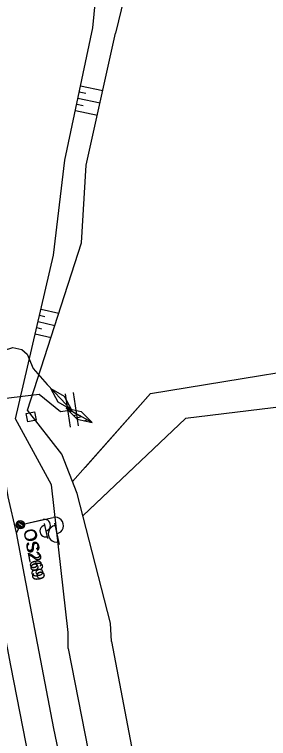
# Model space of a CAD drawing. Extents: x -545967 to -545044, y -1122650 to -1118491.
# Drawn here: x -545802.1 to -545771.9, y -1118710.2 to -1118624.1 of the extents above; entities that cross this region are included whole.
import ezdxf

# ---------------------------------------------------------------- set-up
doc = ezdxf.new("R2010")
doc.units = 0
for name, color, linetype in [('Vrstva 1', 7, 'Continuous'), ('Vrstva 25', 7, 'Continuous'), ('Vrstva 25 - silnoproud prvky', 7, 'Continuous'), ('Vrstva 26', 7, 'Continuous'), ('Vrstva 26 - silnoproud', 7, 'Continuous'), ('Vrstva 31', 7, 'Continuous'), ('Vrstva 41', 7, 'Continuous'), ('Vrstva 42', 7, 'Continuous'), ('Vrstva 48', 7, 'Continuous'), ('Vrstva 49', 7, 'Continuous'), ('Vrstva 62', 7, 'Continuous')]:
    doc.layers.add(name, color=color, linetype=linetype)

msp = doc.modelspace()

# ---------------------------------------------------------------- linework, layer by layer
at = {"layer": 'Vrstva 1'}
msp.add_lwpolyline([(-545803.343, -1118697.361), (-545802.529, -1118701.559), (-545796.372, -1118733.137), (-545788.892, -1118771.626), (-545784.123, -1118796.192), (-545777.723, -1118829.089), (-545771.163, -1118862.699), (-545764.792, -1118895.381), (-545757.603, -1118932.309), (-545753.441, -1118953.648), (-545749.904, -1118971.286), (-545746.403, -1118987.4), (-545742.64, -1119003.664), (-545739.307, -1119017.411), (-545735.997, -1119030.103), (-545730.526, -1119049.438)], dxfattribs=at)
at = {"layer": 'Vrstva 25'}
for p, q in [((-545800.899, -1118684.702), (-545797.485, -1118683.93)), ((-545801.866, -1118684.675), (-545801.056, -1118685.186)), ((-545801.635, -1118684.378), (-545800.891, -1118684.847)), ((-545797.331, -1118684.613), (-545796.758, -1118687.149))]:
    msp.add_line(p, q, dxfattribs=at)
msp.add_circle((-545801.387, -1118684.812), 0.5, dxfattribs=at)
msp.add_circle((-545801.387, -1118684.812), 0.5, dxfattribs=at)
for centre, start, end in [((-545797.265, -1118684.905), 282.73998, 102.73998), ((-545797.056, -1118685.883), 102.0374, 283.44255)]:
    msp.add_arc(centre, 1, start, end, dxfattribs=at)
at = {"layer": 'Vrstva 25 - silnoproud prvky'}
for p, q in [((-545801.722, -1118684.716), (-545801.156, -1118685.074)), ((-545801.56, -1118684.508), (-545801.04, -1118684.837)), ((-545801.046, -1118684.735), (-545798.656, -1118684.195)), ((-545798.548, -1118684.672), (-545798.147, -1118686.448))]:
    msp.add_line(p, q, dxfattribs=at)
msp.add_circle((-545801.387, -1118684.812), 0.35, dxfattribs=at)
for centre, start, end in [((-545798.356, -1118685.562), 102.0374, 283.44255), ((-545798.502, -1118684.877), 282.73998, 102.73998)]:
    msp.add_arc(centre, 0.7, start, end, dxfattribs=at)
at = {"layer": 'Vrstva 26'}
for points in [[(-545795.14, -1118719.856), (-545797.401, -1118709.038), (-545800.896, -1118690.8), (-545801.851, -1118685.761), (-545802.818, -1118681.484), (-545803.86, -1118675.25), (-545805.172, -1118668.631), (-545806.131, -1118665.54), (-545807.231, -1118660.35), (-545808.894, -1118651.177), (-545811.62, -1118637.176), (-545812.724, -1118631.013), (-545813.605, -1118626.947), (-545815.439, -1118615.53)], [(-545801.851, -1118685.761), (-545801.379, -1118684.924), (-545801.387, -1118684.812)]]:
    msp.add_lwpolyline(points, dxfattribs=at)
at = {"layer": 'Vrstva 26 - silnoproud'}
for points in [[(-545795.14, -1118719.856), (-545797.401, -1118709.038), (-545800.896, -1118690.8), (-545801.851, -1118685.761), (-545802.818, -1118681.484), (-545803.86, -1118675.25), (-545805.172, -1118668.631), (-545806.131, -1118665.54), (-545807.231, -1118660.35), (-545808.894, -1118651.177), (-545811.62, -1118637.176), (-545812.724, -1118631.013), (-545813.605, -1118626.947), (-545815.439, -1118615.53)], [(-545801.851, -1118685.761), (-545801.379, -1118684.924), (-545801.387, -1118684.812)]]:
    msp.add_lwpolyline(points, dxfattribs=at)
at = {"layer": 'Vrstva 31'}
for p, q in [((-545795.834, -1118671.051), (-545795.77, -1118671.046)), ((-545795.545, -1118671.356), (-545795.324, -1118671.291)), ((-545795.075, -1118671.822), (-545794.607, -1118671.686)), ((-545794.762, -1118672.119), (-545794.145, -1118671.941)), ((-545793.799, -1118672.443), (-545793.429, -1118672.335)), ((-545793.057, -1118672.602), (-545792.984, -1118672.58))]:
    msp.add_line(p, q, dxfattribs=at)
for points in [[(-545850.96, -1118681.13), (-545850.51, -1118680.46), (-545848.78, -1118676.81), (-545847.44, -1118674.83), (-545847.15, -1118673.7), (-545846.77, -1118673.1), (-545844.1, -1118672.89), (-545832.3, -1118671.48), (-545826.35, -1118670.63), (-545811.42, -1118666.68), (-545802.26, -1118663.75), (-545801.2, -1118663.96), (-545800.56, -1118664.54), (-545799.84, -1118666.21), (-545798.21, -1118668.15), (-545796.54, -1118669.87), (-545795.09, -1118671.42), (-545794.4, -1118671.8)], [(-545850.96, -1118681.13), (-545850.51, -1118680.46), (-545848.78, -1118676.81), (-545847.44, -1118674.83), (-545847.15, -1118673.7), (-545846.77, -1118673.1), (-545844.1, -1118672.89), (-545832.3, -1118671.48), (-545826.35, -1118670.63), (-545811.42, -1118666.68), (-545802.26, -1118663.75), (-545801.2, -1118663.96), (-545800.56, -1118664.54), (-545799.84, -1118666.21), (-545798.21, -1118668.15), (-545796.54, -1118669.87), (-545795.09, -1118671.42), (-545794.4, -1118671.8)], [(-545797.759, -1118668.614), (-545796.181, -1118669.522), (-545795.321, -1118671.126), (-545796.899, -1118670.218), (-545797.759, -1118668.614)], [(-545795.943, -1118670.95), (-545794.154, -1118671.354), (-545792.857, -1118672.65)]]:
    msp.add_lwpolyline(points, dxfattribs=at)
msp.add_lwpolyline([(-545795.943, -1118670.95), (-545794.646, -1118672.246), (-545792.857, -1118672.65)], close=True, dxfattribs=at)
at = {"layer": 'Vrstva 41'}
for p, q in [((-545796.035, -1118669.243), (-545795.473, -1118673.203)), ((-545794.483, -1118673.063), (-545795.045, -1118669.103))]:
    msp.add_line(p, q, dxfattribs=at)
msp.add_lwpolyline([(-545799.686, -1118671.378), (-545799.494, -1118672.36), (-545800.476, -1118672.552), (-545800.668, -1118671.57), (-545799.686, -1118671.378)], dxfattribs=at)
at = {"layer": 'Vrstva 42'}
msp.add_lwpolyline([(-545847.978, -1118676.939), (-545826.574, -1118673.927), (-545824.998, -1118673.746), (-545823.896, -1118673.62), (-545803.414, -1118669.801), (-545799.147, -1118669.27), (-545796.625, -1118671.347), (-545795.259, -1118671.153)], dxfattribs=at)
at = {"layer": 'Vrstva 48'}
for p, q in [((-545794.219, -1118632.595), (-545791.581, -1118633.155)), ((-545794.531, -1118634.063), (-545791.904, -1118634.62)), ((-545794.375, -1118633.329), (-545793.585, -1118633.497)), ((-545794.687, -1118634.796), (-545793.9, -1118634.963)), ((-545794.842, -1118635.53), (-545792.228, -1118636.085)), ((-545799.088, -1118659.905), (-545798.472, -1118660.049)), ((-545798.918, -1118659.175), (-545796.802, -1118659.668)), ((-545799.258, -1118660.636), (-545797.264, -1118661.1)), ((-545799.428, -1118661.366), (-545798.849, -1118661.501)), ((-545799.599, -1118662.096), (-545797.727, -1118662.533))]:
    msp.add_line(p, q, dxfattribs=at)
at = {"layer": 'Vrstva 49'}
for points in [[(-545795.7, -1118699.528), (-545795.713, -1118697.618), (-545797.684, -1118680.076), (-545801.956, -1118672.207), (-545797.423, -1118652.764), (-545796.1, -1118641.454), (-545792.758, -1118625.711), (-545791.538, -1118613.069)], [(-545790.558, -1118698.682), (-545790.653, -1118696.497), (-545794.631, -1118681.099), (-545796.436, -1118676.426), (-545800.52, -1118671.19), (-545794.1, -1118651.293), (-545793.542, -1118642.044), (-545790.076, -1118626.331)], [(-545790.558, -1118698.682), (-545783.238, -1118737.17), (-545773.95, -1118795.15), (-545740.894, -1118934.351)], [(-545795.7, -1118699.528), (-545788.233, -1118737.742), (-545783.17, -1118774.198), (-545777.676, -1118791.958), (-545766.252, -1118834.896), (-545762.229, -1118863.517), (-545750.538, -1118910.15), (-545748.755, -1118933.679), (-545738.226, -1118978.242), (-545734.453, -1118993.366), (-545726.802, -1119029.271), (-545708.682, -1119069.733), (-545699.17, -1119099.963), (-545685.313, -1119124.181), (-545683.358, -1119136.056), (-545688.074, -1119145.796), (-545688.341, -1119153.091)]]:
    msp.add_lwpolyline(points, dxfattribs=at)
at = {"layer": 'Vrstva 62'}
for points in [[(-545792.042, -1118581.397), (-545791.329, -1118588.996), (-545787.176, -1118605.694), (-545787.338, -1118615.055), (-545790.076, -1118626.331)], [(-545795.177, -1118679.686), (-545785.935, -1118669.185), (-545757.877, -1118664.615), (-545739.736, -1118660.347), (-545734.181, -1118656.62), (-545726.877, -1118663.888), (-545710.495, -1118672.23)], [(-545793.687, -1118677.993), (-545785.935, -1118669.185), (-545757.877, -1118664.615), (-545739.736, -1118660.347), (-545734.181, -1118656.62), (-545726.877, -1118663.888), (-545710.495, -1118672.23)], [(-545712.499, -1118675.414), (-545728.364, -1118666.112), (-545735.6, -1118663.478), (-545756.392, -1118669.069), (-545781.747, -1118672.189), (-545793.943, -1118683.763)], [(-545712.499, -1118675.414), (-545728.364, -1118666.112), (-545735.6, -1118663.478), (-545756.392, -1118669.069), (-545781.747, -1118672.189), (-545793.156, -1118683.016)]]:
    msp.add_lwpolyline(points, dxfattribs=at)

# ---------------------------------------------------------------- texts
at = {"layer": 'Vrstva 25'}
msp.add_text('OS269', height=1.5, rotation=280.73152, dxfattribs=at).set_placement((-545801.026, -1118685.435))
at = {"layer": 'Vrstva 25 - silnoproud prvky'}
msp.add_text('OS269', height=1.4, rotation=280.73152, dxfattribs=at).set_placement((-545801.026, -1118685.435))

doc.saveas('drawing.dxf')
